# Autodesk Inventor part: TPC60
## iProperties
Shininess: 64.0
Length Units: 11272
Angle Units: 11279
Time Units: 11290
Mass Units: 11286
Length Display Precision: 3
Angle Display Precision: 2
Compacted: True
Part Number: TPC60
Document SubType Name: Modeling
Created: 2004-08
Designer: Lori
Manufacturer: Standard
Standards Organization: Custom
Density: 0.0
Volumn: 0.0
Area: 0.0
PropertySet Name: Model Information
Control State: 0
Master: False
Checked Out: False
Author: Lori
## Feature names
1. Base1
